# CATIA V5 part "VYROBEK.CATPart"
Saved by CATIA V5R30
Part number: VYROBEK
Bounding box of the stored display mesh (mm): x -56.028 to 56.028, y -56.028 to 56.028, z -36.619 to 1.271
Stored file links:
  C:\Users\ondra\Desktop\PŘÍLOHA P III\CATIA\VYROBEK.CATPart
  C:\Users\ondra\Desktop\FORMA_BAKALARKA\Part1.CATPart
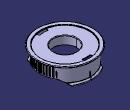
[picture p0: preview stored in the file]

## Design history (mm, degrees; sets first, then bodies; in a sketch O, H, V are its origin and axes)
Body1 (main body)
  Body2 "VYROBEK_ORIGINAL"
    Solid1: linked copy from another document
  Assemble1: tool Body2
